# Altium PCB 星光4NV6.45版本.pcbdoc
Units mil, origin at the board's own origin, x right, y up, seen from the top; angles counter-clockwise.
Board outline 3937.01 x 2047.24 mil, 2 copper layers (Top Layer, Bottom Layer), stack 62.206 mil thick; 34 components, 26 nets, 163 pads, 100 vias.
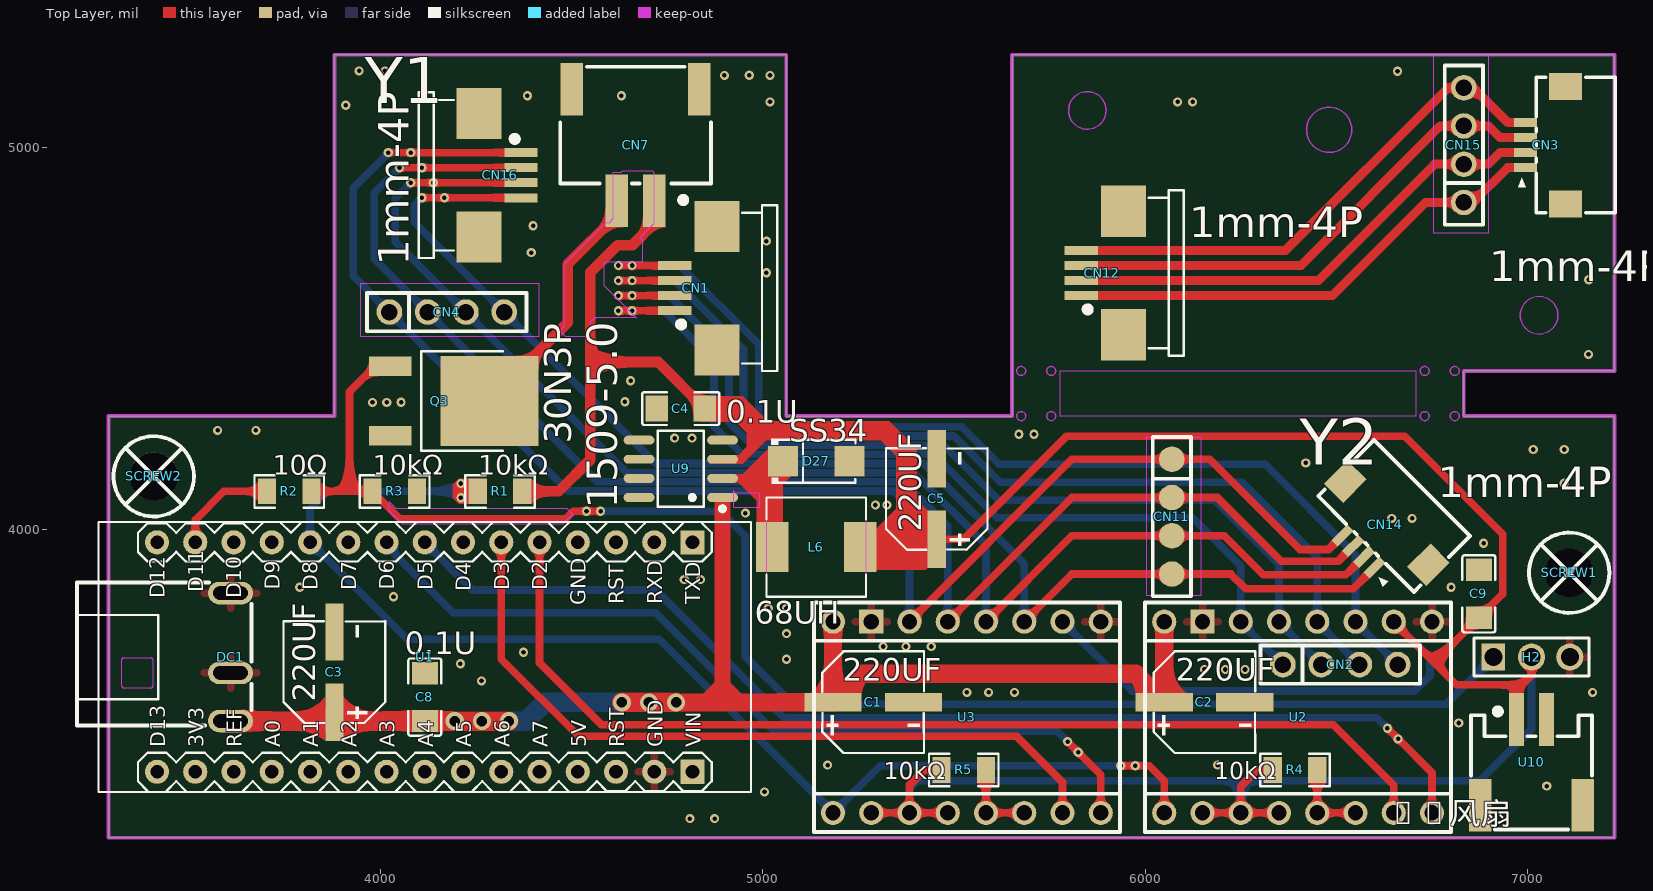
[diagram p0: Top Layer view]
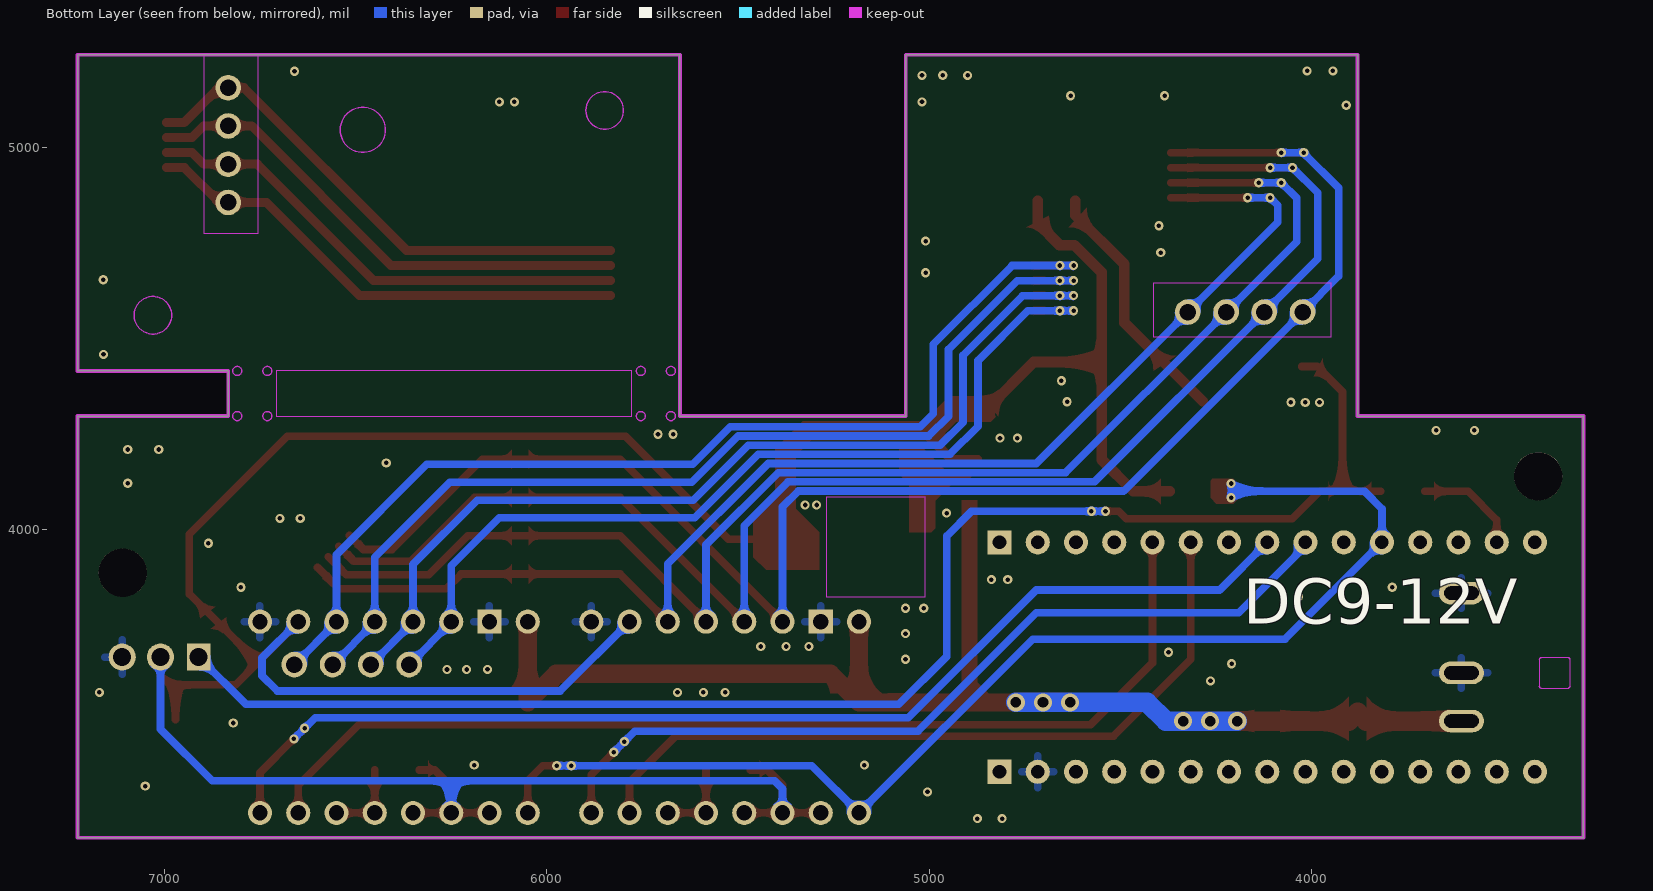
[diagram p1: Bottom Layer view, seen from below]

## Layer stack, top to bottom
Top Solder Mask Layer: solder mask 0.394, Dk 3.3
Top Layer: signal copper 1.379
Dielectric1: surface 59.449, FR4, Dk 4.5
Bottom Layer: signal copper 1.378
Bottom Solder Mask Layer: solder mask 0.394, Dk 3.3

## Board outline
3290,3195 3290,3293.43 3290,4297.36 3880.55,4297.36 3880.55,5242.24 5061.65,5242.24 5061.65,4297.36 5652.2,4297.36 5652.2,5242.24 7227.01,5242.24 7227.01,4415.47 6833.31,4415.47 6833.31,4297.36 7227.01,4297.36 7227.01,3293.43 7227.01,3195

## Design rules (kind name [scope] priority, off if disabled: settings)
BoardOutlineClearance copperThickness1oz [All] p0: genericclearance=10 ignorepadtopadclearanceinfootprint=FALSE except(0: Arc-SplitContinuation Track-SplitContinuation SMDPad-SplitContinuation THPad-SplitContinuation Via-SplitContinuation Fill-SplitContinuation Poly-SplitContinuation Region-SplitContinuation Text-SplitContinuation)
BoardOutlineClearance copperThickness2oz [All] p0: genericclearance=10 ignorepadtopadclearanceinfootprint=FALSE except(0: Arc-SplitContinuation Track-SplitContinuation SMDPad-SplitContinuation THPad-SplitContinuation Via-SplitContinuation Fill-SplitContinuation Poly-SplitContinuation Region-SplitContinuation Text-SplitContinuation)
BoardOutlineClearance Plane_innerPlane [All] p0: genericclearance=10 ignorepadtopadclearanceinfootprint=FALSE except(0: Arc-SplitContinuation Track-SplitContinuation SMDPad-SplitContinuation THPad-SplitContinuation Via-SplitContinuation Fill-SplitContinuation Poly-SplitContinuation Region-SplitContinuation Text-SplitContinuation)
BoardOutlineClearance Copper_copperRegion [All] p0: genericclearance=10 ignorepadtopadclearanceinfootprint=FALSE except(0: Arc-SplitContinuation Track-SplitContinuation SMDPad-SplitContinuation THPad-SplitContinuation Via-SplitContinuation Fill-SplitContinuation Poly-SplitContinuation Region-SplitContinuation Text-SplitContinuation)
BoardOutlineClearance Copper_copperRegion1 [All] p0: genericclearance=10 ignorepadtopadclearanceinfootprint=FALSE except(0: Arc-SplitContinuation Track-SplitContinuation SMDPad-SplitContinuation THPad-SplitContinuation Via-SplitContinuation Fill-SplitContinuation Poly-SplitContinuation Region-SplitContinuation Text-SplitContinuation)
BoardOutlineClearance otherClearance [All] p0: genericclearance=10 ignorepadtopadclearanceinfootprint=FALSE except(0: Arc-SplitContinuation Track-SplitContinuation SMDPad-SplitContinuation THPad-SplitContinuation Via-SplitContinuation Fill-SplitContinuation Poly-SplitContinuation Region-SplitContinuation Text-SplitContinuation)
Clearance copperThickness1oz [All] p1: gap=7 ignorepadtopadclearanceinfootprint=FALSE
Clearance copperThickness2oz [All] p1: gap=7 ignorepadtopadclearanceinfootprint=FALSE
Clearance Plane_innerPlane [All] p1: gap=7 ignorepadtopadclearanceinfootprint=FALSE
Clearance Copper_copperRegion [All] p1: gap=7 ignorepadtopadclearanceinfootprint=FALSE
Clearance Copper_copperRegion1 [All] p1: gap=7 ignorepadtopadclearanceinfootprint=FALSE
Clearance otherClearance [All] p1: gap=7 ignorepadtopadclearanceinfootprint=FALSE
DiffPairsRouting differentialPair [All] p1: maxuncoupledlength=10 minlimit=5.9843 maxlimit=Infinity mostfreqgap=5.9843 toplayer_minwidth=5 toplayer_prefwidth=10 toplayer_maxwidth=100 bottomlayer_minwidth=5 bottomlayer_prefwidth=10 bottomlayer_maxwidth=100
PasteMaskExpansion pasteMaskExpansion [All] p1: expansion=0
PlaneConnect innerPlane [All] p1: planeconnectstyle=Relief reliefexpansion=20 reliefentries=4 reliefconductorwidth=10 reliefairgap=10
PolygonConnect copperRegion [All] p1: connectstyle=Relief reliefentries=4 reliefconductorwidth=10 polygonreliefangle="90 Angle" airgapwidth=10
PolygonConnect copperRegion1 [All] p1: connectstyle=Relief reliefentries=4 reliefconductorwidth=19.685 polygonreliefangle="90 Angle" airgapwidth=10
RoutingVias viaSize [All] p1: viastyle="Through Hole" holewidth=12.0078 minholewidth=11.811 maxholewidth=248.0314 width=12.0078 minwidth=11.811 maxwidth=248.0314
SolderMaskExpansion solderMaskExpansion [All] p1: useseparateexpansions=TRUE expansion=2.0079 expansionbottom=2.0079
Width copperThickness1oz [All] p1: maxlimit=100 minlimit=5 preferedwidth=20
Width copperThickness2oz [All] p1: maxlimit=100 minlimit=5 preferedwidth=10

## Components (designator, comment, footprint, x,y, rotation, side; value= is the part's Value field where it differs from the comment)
C1 "" CAP-SMD_BD6.3-L6.6-W6.6-FD-1 5289.21,3549.33 r0 top
C2 "" CAP-SMD_BD6.3-L6.6-W6.6-FD-1 6155.36,3549.33 r0 top
C3 "220uF" CAP-SMD_BD6.3-L6.6-W6.6-FD-1 3880.55,3628.07 r90 top
C4 "100nF" C1206 4786.06,4317.05 r0 top
C5 "" CAP-SMD_BD6.3-L6.6-W6.6-FD-1 5455.35,4080.83 r90 top
C8 "" C1206 4116.77,3562.82 r270 top
C9 "" C1206 6872.68,3832.8 r270 top
CN1 "" FPC-SMD_4P-P1.00_AFA07-S04ECC-00 4825.43,4632.01 r90 top
CN2 "" HDR-TH_4P-P2.54-V-F#1 6510.47,3647.76 r0 top
CN3 "" FPC-SMD_4P-P1.00_10A20L04P 7049.84,5006.02 r90 top
CN4 "" HDR-TH_4P-P2.54-V-F#1 4174.37,4569.45 r0 top
CN7 "" CONN-SMD_2P-P2.54_MEGASTAR_ZX-XH2.54-2PWT 4667.95,5006.02 r180 top
CN11 "" HDR-TH_4P-P2.54-V-F#2 6070,4034.45 r270 top
CN12 "" FPC-SMD_4P-P1.00_AFA07-S04ECC-00 5888.43,4671.38 r90 top
CN14 "" FPC-SMD_4P-P1.00_10A20L04P 6597.09,3982.4 r135 top
CN15 "" HDR-TH_4P-P2.54-V-F#1 6833.31,5006.02 r90 top
CN16 "" FPC-SMD_4P-P1.00_AFA07-S04ECC-00 4313.62,4927.28 r270 top
D27 "" SMA_L4.3-W2.6-LS5.2-RD 5140.39,4179.25 r0 top
DC1 "" DC-IN-TH_DC044 3608.9,3667.44 r0 top
H2 "" HDR-TH_3P-P2.54-V-M-1 7010.47,3667.44 r0 top
L6 "" IND-SMD_L7.1-W6.6_H5.0 5140.39,3954.84 r180 top
Q3 "" TO-252-2_L6.6-W6.1-P4.60-LS10.0-BR-CW 4156.14,4336.73 r180 top
R1 "10kΩ" R1206 4313.62,4100.51 r0 top
R2 "10Ω" R1206 3762.44,4100.51 r180 top
R3 "10kΩ" R1206 4038.03,4100.51 r180 top
R4 "10kΩ" R1206 6392.02,3372.17 r180 top
R5 "10kΩ" R1206 5525.87,3372.17 r180 top
SCREW1 "" M3螺丝 7108.9,3887.91 r0 top
SCREW2 "" M3螺丝 3408.11,4139.88 r0 top
U1 "" COMM-TH_ARDUINO_NANO 4116.77,3667.44 r0 top
U2 "" DIP-16_L20.3-W15.2-P2.54_LS12.7_A4988 6400.24,3509.96 r90 top
U3 "" DIP-16_L20.3-W15.2-P2.54_LS12.7_A4988 5534.09,3509.96 r90 top
U9 "" SOIC-8_L4.9-W3.9-P1.27-LS6.0-BL 4786.06,4159.57 r90 top
U10 "" CONN-SMD_ZX-PH2.0-WT2P 7010.47,3391.85 r0 top

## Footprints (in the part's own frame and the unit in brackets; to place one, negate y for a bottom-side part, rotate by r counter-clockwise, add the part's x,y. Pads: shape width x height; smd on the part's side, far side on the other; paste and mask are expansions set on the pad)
C1206 [mm]
  rect 1.485x1.728 smd: 1(-1.593,0) 2(1.593,0)
  silkscreen extent -2.56,-1.09 2.56,1.09
CAP-SMD_BD6.3-L6.6-W6.6-FD-1 [mm]
  rect 3.8x1.2 smd: 1(-2.67,0) 2(2.67,0)
  silkscreen extent -3.38,-3.38 3.38,3.38
COMM-TH_ARDUINO_NANO [mm]
  rect 1.6x1.6 hole 0.9: 1(17.78,7.62) 30(17.78,-7.62)
  round 1.6 hole 0.9: 2(15.24,7.62) 4(10.16,7.62) 6(5.08,7.62) 8(0,7.62) 10(-5.08,7.62) 12(-10.16,7.62) 14(-15.24,7.62) 15(-17.78,7.62) 16(-17.78,-7.62) 18(-12.7,-7.62) 20(-7.62,-7.62) 22(-2.54,-7.62) 24(2.54,-7.62) 26(7.62,-7.62) 28(12.7,-7.62) 29(15.24,-7.62)
  round 1.6 hole 0.9 copper offset 0,0: 3(12.7,7.62)
  round 1.6 hole 0.9 copper offset -0.001,0: 5(7.621,7.62) 7(2.541,7.62) 9(-2.539,7.62) 11(-7.619,7.62) 13(-12.699,7.62)
  round 1.6 hole 0.9 copper offset 0.001,0: 17(-15.241,-7.62) 19(-10.161,-7.62) 21(-5.081,-7.62) 23(-0.001,-7.62) 25(5.079,-7.62) 27(10.159,-7.62)
  silkscreen extent -23.11,-8.97 21.67,8.97
CONN-SMD_2P-P2.54_MEGASTAR_ZX-XH2.54-2PWT [mm]
  rect 1.5x3.5 smd: 1(-1.25,3.7) 2(1.25,3.7) 3(-4.23,-3.7) 4(4.23,-3.7)
  silkscreen extent -5,-5.21 5,3.85
CONN-SMD_ZX-PH2.0-WT2P [mm]
  rect 1x3.5 smd: 1(-1,2.85) 2(1,2.85)
  rect 1.5x3.5 smd: 3(-3.4,-2.85) 4(3.4,-2.85)
  silkscreen extent -4.02,-4.44 4.02,3.59
DC-IN-TH_DC044 [mm]
  oval 3x1.5 hole 0.9 slot 2.3 at 0 deg: 2(0,4.25) 3(0,-1.05) 4(0,-4.25)
  Board Outline Layer lines w0.003: -7.209,-1.939 -7.209,-0.161 cw(c-7.082,-0.161) -7.082,-0.034 -5.304,-0.034 cw(c-5.304,-0.161) -5.177,-0.161 -5.177,-1.939 cw(c-5.304,-1.939) -5.304,-2.066 -7.082,-2.066 cw(c-7.082,-1.939) -7.209,-1.939
  Board Outline Layer region: -7.209,-1.939 -7.209,-0.161 -7.199,-0.112 -7.172,-0.071 -7.131,-0.044 -7.082,-0.034 -7.082,-0.034 -5.304,-0.034 -5.255,-0.044 -5.214,-0.071 -5.187,-0.112 -5.177,-0.161 -5.177,-0.161 -5.177,-1.939 -5.187,-1.988 -5.214,-2.029 -5.255,-2.056 -5.304,-2.066 -5.304,-2.066 -7.082,-2.066 -7.131,-2.056 -7.172,-2.029 -7.199,-1.988 -7.209,-1.939
  Board Outline Layer region: -7.209,-1.939 -7.209,-0.161 -7.199,-0.112 -7.172,-0.071 -7.131,-0.044 -7.082,-0.034 -7.082,-0.034 -5.304,-0.034 -5.255,-0.044 -5.214,-0.071 -5.187,-0.112 -5.177,-0.161 -5.177,-0.161 -5.177,-1.939 -5.187,-1.988 -5.214,-2.029 -5.255,-2.056 -5.304,-2.066 -5.304,-2.066 -7.082,-2.066 -7.131,-2.056 -7.172,-2.029 -7.199,-1.988 -7.209,-1.939
  silkscreen extent -10.2,-4.55 1.4,4.95
DIP-16_L20.3-W15.2-P2.54_LS12.7_A4988 [mm]
  round 1.6 hole 1.02: 1(-6.35,8.89) 2(-6.35,6.35) 3(-6.35,3.81) 4(-6.35,1.27) 5(-6.35,-1.27) 6(-6.35,-3.81) 7(-6.35,-6.35) 8(-6.35,-8.89) 9(6.35,-8.89) 10(6.35,-6.35) 11(6.35,-3.81) 12(6.35,-1.27) 13(6.35,1.27) 14(6.35,3.81) 16(6.35,8.89)
  rect 1.6x1.6 hole 1.02: 15(6.35,6.35)
  silkscreen extent -7.62,-10.16 7.62,10.16
FPC-SMD_4P-P1.00_10A20L04P [mm]
  rect 0.6x1.5 smd: 1(-1.5,1.4) 2(-0.5,1.4) 3(0.5,1.4) 4(1.5,1.4)
  rect 1.8x2.2 smd: 5(3.9,-1.263) 6(-3.9,-1.263)
  silkscreen extent -4.5,-4.56 4.5,1.9
FPC-SMD_4P-P1.00_AFA07-S04ECC-00 [mm]
  rect 0.6x2.2 smd: 1(-1.5,1.4) 2(-0.5,1.4) 3(0.5,1.4) 4(1.5,1.4)
  rect 3.4x3 smd: 5(4.1,-1.4) 6(-4.1,-1.4)
  silkscreen extent -5.5,-5.4 5.5,1.17
HDR-TH_3P-P2.54-V-M-1 [mm]
  rect 1.575x1.8 hole 1.2: 1(-2.54,0)
  round 1.8 hole 1.2: 2(0,0) 3(2.54,0)
  silkscreen extent -3.81,-1.27 3.81,1.27
HDR-TH_4P-P2.54-V-F#1 [mm]
  round 1.7 hole 1.1: 1(-3.81,0) 2(-1.27,0) 3(1.27,0) 4(3.81,0)
  silkscreen extent -5.29,-1.27 5.29,1.27
HDR-TH_4P-P2.54-V-F#2 [mm]
  round 1.7 smd: 1(-3.81,0) 2(-1.27,0) 3(1.27,0) 4(3.81,0)
  silkscreen extent -5.29,-1.27 5.29,1.27
IND-SMD_L7.1-W6.6_H5.0 [mm]
  rect 2.15x3.32 smd: 1(-2.913,0) 2(2.913,0)
  silkscreen extent -3.3,-3.3 3.3,3.3
M3螺丝 [mil]
  round 126 hole 126: 1(0,0)
  silkscreen extent -105,-105 105,105
R1206 [mil]
  rect 47.54x66.97 smd: 1(-58.22,0) 2(58.22,0)
  silkscreen extent -91,-42 91,42
SMA_L4.3-W2.6-LS5.2-RD [mm]
  rect 2x2 smd: 1(-2.2,0) 2(2.2,0)
  silkscreen extent -2.98,-1.5 2.6,1.5
SOIC-8_L4.9-W3.9-P1.27-LS6.0-BL [mm]
  oval 0.588x2.045 smd: 1(-1.905,-2.772) 2(-0.635,-2.772) 3(0.635,-2.772) 4(1.905,-2.772) 5(1.905,2.772) 6(0.635,2.772) 7(-0.635,2.772) 8(-1.905,2.772)
  silkscreen extent -2.8,-2.92 2.53,1.52
TO-252-2_L6.6-W6.1-P4.60-LS10.0-BR-CW [mm]
  rect 2.8x1.3 smd: 1(3.292,-2.3) 3(3.292,2.3)
  rect 6.5x6 smd: 2(-3.292,0)
  silkscreen extent -4.17,-3.3 1.23,3.3

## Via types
v1: diameter 24.02, hole 12.01, Top Layer to Bottom Layer, 94 vias
v2: diameter 47.24, hole 27.56, Top Layer to Bottom Layer, 6 vias

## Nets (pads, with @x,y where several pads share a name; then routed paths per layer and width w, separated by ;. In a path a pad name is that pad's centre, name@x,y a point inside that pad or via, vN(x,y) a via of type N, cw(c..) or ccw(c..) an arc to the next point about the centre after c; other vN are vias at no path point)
5V: C4.2 C5.1 C9.2 CN7.1 H2.2 L6.1 R1.2 R4.2 R5.2 U2.2 U2.3 U2.4 U2.10 U3.2 U3.3 U3.4 U3.10 U9.3 U10.1 | length 8164.9
  Top Layer w20: U3.2 U3.3 ; C5.1 5525.26,3975.71 5794.56,4245 6678.82,4245 6935,3988.82 6935,3832.42 C9.2 6768.05,3665.47 ; R5.2 5423.35,3372.17 5384.09,3332.91 U3.3 ; U3.4 U3.3 ; U2.2 U2.3 ; R4.2 6293.35,3372.17 6250.24,3329.06 U2.3 ; U2.4 U2.3 ; U2.10 6650.24,3758.58 6743.35,3665.47 ; U10.1 6971.1,3579.92 ; H2.2 7010.47,3619.29 6986.35,3595.17 ; 6743.35,3665.47 6768.05,3665.47 ; 6743.35,3665.47 6768.05,3640.77 ; 6768.05,3640.77 6768.05,3665.47 ; 6768.05,3640.77 6813.65,3595.17 6955.84,3595.17 ; 6955.84,3595.17 6971.1,3579.92 ; 6955.84,3595.17 6986.35,3595.17 ; 6971.1,3579.92 6986.35,3595.17
  Top Layer w27.56: R1.2 4466.69,4100.51 4550,4183.82 4550,4414.05 ; 4574.77,4438.82 4550,4414.05 ; CN7.1 4717.17,4802.01 4659.82,4744.66 4620.84,4744.66 4550,4673.82 4550,4463.82 ; C4.2 4726.99,4438.82 4575,4438.82 4550,4463.82 ; 4550,4414.05 4550,4463.82
  Bottom Layer w20: U3.3 5384.09,3322.91 5405,3343.82 6227.74,3343.82 ; U3.10 5965.24,3578.82 6705,3578.82 6745,3618.82 6745,3665.2 U2.10 ; U2.3 6250.24,3321.32 ; H2.2 7010.47,3479.29 6875,3343.82 6272.74,3343.82 ; 6227.74,3343.82 6250.24,3321.32 ; 6227.74,3343.82 6272.74,3343.82 ; 6250.24,3321.32 6272.74,3343.82
12V: C1.1 C2.1 C3.1 C8.2 DC1.4 U2.16 U3.16 U9.1 | length 3246.9
  Top Layer w47.24: v2(4773.79,3548.82) 5183.58,3548.82 C1.1 ; U3.16 C1.1 ; U2.16 C2.1 5975.75,3623.82 5258.58,3623.82 C1.1
  Top Layer w51.18: DC1.4 3857.72,3500.12 C3.1 3903.38,3500.12 C8.2 v2(4195.08,3500.12) v2(4265.9,3500.12) v2(4336.72,3500.12) ; v2(4632.15,3548.82) v2(4702.97,3548.82) v2(4773.79,3548.82)
  Bottom Layer w51.18: v2(4195.08,3500.12) v2(4265.9,3500.12) v2(4336.72,3500.12) 4381.82,3500.12 4430.51,3548.82 v2(4632.15,3548.82) v2(4702.97,3548.82) v2(4773.79,3548.82)
$1N38281: R5.1 U3.5 U3.6 | length 212.2
  Top Layer w20: R5.1 U3.5 U3.6
$1N38618: CN4.4 CN11.4 CN14.1 CN16.4 U3.11 | length 3512.4
  Top Layer w20: v1(4109.35,4868.23) v1(4168.06,4868.23) CN16.4 ; U3.11 5808.58,3884.45 CN11.4 6224.51,3884.45 6263.04,3845.91 6544.12,3845.91 CN14.1
  Bottom Layer w20: v1(4168.06,4868.23) v1(4109.35,4868.23) 4089.35,4848.23 4089.35,4804.46 CN4.4 4720.31,4173.5 5421.5,4173.5 5684.09,3910.91 U3.11
$1N38619: CN4.3 CN11.3 CN14.2 CN16.3 U3.12 | length 3734.1
  Top Layer w20: v1(4080,4907.6) v1(4138.71,4907.6) CN16.3 ; U3.12 5808.58,3984.45 CN11.3 6206.6,3984.45 6308.76,3882.28 6524.81,3882.28 CN14.2
  Bottom Layer w20: v1(4138.71,4907.6) v1(4080,4907.6) 4040,4867.6 4040,4753.82 CN4.3 4644.33,4149.49 5395.51,4149.49 5584.09,3960.91 U3.12
$1N38620: CN4.2 CN11.2 CN14.3 CN16.2 U3.13 | length 3961.3
  Top Layer w20: v1(4050.65,4946.97) v1(4109.35,4946.97) CN16.2 ; U3.13 5808.58,4084.45 CN11.2 6189.37,4084.45 6356.2,3917.62 6504.46,3917.62 CN14.3
  Bottom Layer w20: v1(4109.35,4946.97) v1(4050.65,4946.97) 3985,4881.32 3985,4708.82 CN4.2 4568.35,4125.47 5369.53,4125.47 5484.09,4010.91 U3.13
$1N38622: CN4.1 CN11.1 CN14.4 CN16.1 U3.14 | length 4190.7
  Top Layer w20: v1(4021.29,4986.33) v1(4080,4986.33) CN16.1 ; U3.14 5808.58,4184.45 CN11.1 6169.37,4184.45 6405,3948.82 6479.99,3948.82 CN14.4
  Bottom Layer w20: v1(4080,4986.33) 4022.51,4986.33 3930,4893.82 3930,4663.82 CN4.1 4492.36,4101.46 5342.6,4101.46 5384.09,4059.96 U3.14
$1N39292: R4.1 U2.5 U2.6 | length 212.2
  Top Layer w20: R4.1 U2.5 U2.6
$1N39467: CN1.4 CN2.4 U2.11 | length 2792.9
  Top Layer w20: v1(4623.04,4691.06) v1(4658.9,4691.06) CN1.4@4730.94,4691.06 ; CN2.4@6662.44,3647.76 CN2.4@6668.35,3647.76
  Bottom Layer w20: v1(4623.04,4691.06) v1(4658.9,4691.06) 4783.92,4691.06 4990.09,4484.89 4990.09,4303.72 5024.25,4269.57 5520.43,4269.57 5618.9,4171.1 6313.7,4171.1 6550.24,3934.56 U2.11 6550.24,3757.99 CN2.4
$1N39468: CN1.3 CN2.3 U2.12 | length 2664.2
  Top Layer w20: v1@4622.14,4651.69 v1(4658.9,4651.69) CN1.3@4730.94,4651.69
  Bottom Layer w20: v1(4623.04,4651.69) v1(4658.9,4651.69) 4770.19,4651.69 4950,4471.88 4950,4296.82 5001.27,4245.55 5499.45,4245.55 5620.92,4124.08 6254.15,4124.08 6450.24,3927.98 U2.12 6450.24,3757.99 CN2.3
$1N39469: CN1.1 CN2.1 U2.14 | length 2415.7
  Top Layer w20: v1(4623.04,4572.96) v1(4658.9,4572.96) CN1.1@4730.94,4572.96
  Bottom Layer w20: v1(4623.04,4572.96) v1(4658.9,4572.96) 4742.65,4572.96 4872.76,4442.86 4872.76,4271.06 4946.3,4197.52 5447.48,4197.52 5613.7,4031.3 6124.63,4031.3 6250.24,3905.69 U2.14 6250.24,3757.99 CN2.1
$1N39470: CN1.2 CN2.2 U2.13 | length 2535.3
  Top Layer w20: v1@4623.94,4612.32 v1(4658.9,4612.32) CN1.2@4730.94,4612.32
  Bottom Layer w20: v1(4623.04,4612.32) v1(4658.9,4612.32) 4756.5,4612.32 4912.05,4456.76 4912.05,4281.76 4972.28,4221.54 5473.46,4221.54 5617.49,4077.51 6182.29,4077.51 6350.24,3909.56 U2.13 6350.24,3757.99 CN2.2
$1N40367: CN7.2 Q3.2 | length 661.6
  Top Layer w27.56: Q3.2 4490,4540.98 4490,4694.31 4618.74,4823.05 CN7.2
$1N40669: H2.1 Q3.1 R2.1 R3.2 | length 4045.4
  Top Layer w20: R2.1 3897.44,4100.51 ; Q3.1 3985.99,4427.28 3920,4361.29 3920,4123.07 ; v1(4576.5,4048.82) v1(4539.71,4048.82) 4505,4048.82 4485,4028.82 4051.5,4028.82 R3.2 3942.56,4100.51 ; 3897.44,4100.51 3920,4123.07 ; 3897.44,4100.51 3942.56,4100.51 ; 3920,4123.07 3942.56,4100.51
  Bottom Layer w20: v1(4539.71,4048.82) v1(4576.5,4048.82) 4890,4048.82 4955,3983.82 4955,3668.82 5080,3543.82 6786.85,3543.82 H2.1
$1N43520: D27.1 L6.2 U9.2
$1N45498: CN3.4 CN12.4 CN15.4 | length 1375.4
  Top Layer w23.62: CN12.4 6366.61,4730.43 6792.2,5156.02 CN15.4 6857.8,5156.02 6948.74,5065.08 CN3.4
$1N45502: CN3.3 CN12.3 CN15.3 | length 1325.1
  Top Layer w23.62: CN12.3 6407.24,4691.06 6772.2,5056.02 CN15.3 6897.8,5056.02 6928.11,5025.71 CN3.3
$1N45507: CN3.2 CN12.2 CN15.2 | length 1300
  Top Layer w23.62: CN12.2 6452.87,4651.69 6757.2,4956.02 CN15.2 6897.2,4956.02 6927.52,4986.34 CN3.2
$1N45512: CN3.1 CN12.1 CN15.1 | length 1300
  Top Layer w23.62: CN12.1 6489.62,4612.33 6733.31,4856.02 CN15.1 6857.2,4856.02 6948.15,4946.97 CN3.1
D2/X-STEP: U1.5 U2.7 | length 2753.3
  Top Layer w20: U1.5 4416.77,3652.05 4578.82,3490 6492.02,3490 6650.24,3331.78 U2.7
D3/Y-STEP: U1.6 U3.7 | length 1986
  Top Layer w20: U1.6 4316.77,3662.05 4518.82,3460 5663.82,3460 5784.09,3339.72 U3.7
D5/X-DIR: U1.8 U2.8 | length 3027.5
  Top Layer w20: v1(6633.47,3481.49) v1(6661.51,3453.45) 6750.24,3364.73 U2.8
  Bottom Layer w20: U1.8 4241.4,3842.82 4721,3842.82 5055,3508.82 6606.14,3508.82 v1(6633.47,3481.49) v1(6661.51,3453.45)
D6/Y-DIR: U1.9 U3.8 | length 2259
  Top Layer w20: v1(5797.33,3446.49) v1(5825.37,3418.45) 5884.09,3359.72 U3.8
  Bottom Layer w20: U1.9@4013.69,3961.25 4191.63,3783.31 4720.51,3783.31 5030,3473.82 5770,3473.82 v1(5797.33,3446.49) v1(5825.37,3418.45)
D8/EN: R1.1 U1.11 U2.1 U3.1 | length 3289.8
  Top Layer w20: v1(5936.52,3383.15) v1(5974.33,3383.15) 6010.67,3383.15 6050.24,3343.58 U2.1
  Bottom Layer w20: v1(5974.33,3383.15) v1(5936.52,3383.15) 5307.28,3383.15 U3.1 4730.24,3713.82 4070.39,3713.82 U1.11 3816.77,4055.59 3862.5,4101.32 4191.14,4101.32 ; 4191.14,4101.32 v1(4211.14,4121.32) v1(4211.14,4083.82) 4193.64,4101.32 4191.14,4101.32
D11/PWM: R2.2 U1.14 | length 276.6
  Top Layer w20: U1.14 3516.77,4025.59 3591.69,4100.51 R2.2
GND: C1.2 C2.2 C3.2 C4.1 C5.2 C8.1 C9.1 CN1.5 CN1.6 CN3.5 CN3.6 CN7.3 CN7.4 CN12.5 CN12.6 CN14.5 CN14.6 CN16.5 CN16.6 D27.2 DC1.2 DC1.3 H2.3 Q3.3 R3.1 U1.29 U2.9 U2.15 U3.9 U3.15 U9.4 U9.5 U9.6 U9.7 U9.8 U10.2 U10.3 U10.4
  other v1: 4810,3245 4874.41,3245 5005,3315 7050,3330 5170,3385 6190,3385 6820,3495 5534.09,3574.9 5590.98,3574.9 5658.52,3574.9 7170,3575 4265,3605 6155.36,3635.18 6210,3635 6261.37,3635 4210,3650 5062.52,3661.7 4375,3680 5315,3695 5374.69,3695 5441.14,3695 5062.52,3728.69 5015,3795 5062.52,3795 4035,3825 3790,3850 6800,3850 4795,3870 4837.86,3870 6885,3965 6645,4030 6698.27,4030 4955.18,4043.76 5295,4065 5325,4065 7095.9,4121.88 6420,4175 7015,4210 7095.9,4210 4770,4240 4815.48,4240 5670,4250 5709.73,4250 3575,4260 3675.22,4260 3980,4333.19 4017.5,4333.19 4055,4333.82 4640,4335 4655,4390 7159.37,4458.82 7160,4653.82 5010,4672.38 4395,4725 5010,4755 4400,4795 3910,5110 5019.37,5118.82 6085,5118.82 6124.37,5118.82 4385,5135 4630.96,5135 4900,5188.19 5019.37,5188.19 4965,5188.82 6660,5198.82 3945,5200 4012.52,5200
pads on no net: SCREW1.1 SCREW2.1 U1.1 U1.2 U1.3 U1.4 U1.7 U1.10 U1.12 U1.13 U1.15 U1.16 U1.17 U1.18 U1.19 U1.20 U1.21 U1.22 U1.23 U1.24 U1.25 U1.26 U1.27 U1.28 U1.30

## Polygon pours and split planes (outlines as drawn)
GND on Top Layer (solid, remove dead copper, pour order 0): 3100,5350 7380,5350 7380,3100 3100,3100
GND on Bottom Layer (solid, remove dead copper, pour order 2): 3000,5450 7430,5450 7430,3000 3000,3000

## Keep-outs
Top Layer:
  region: 4634.12,4939.12 4710.88,4939.12 4715,4935 4715,4799.84 4679.14,4763.98 4685,4758.12 4685,4700 4590,4700 4585,4695 4585,4640 4670,4555 4562.62,4555 4550,4542.38 4550,4515 4540,4505 4485.92,4505 4469.97,4520.95 4481.35,4532.33 4481.35,4694.31 4589.79,4802.74 4598.44,4802.74 4610,4814.31 4610,4935 4630,4935
  region: 4923.09,4102.7 4923.09,4059.74 4992.1,4059.74 4992.1,4093.81 4989.56,4096.35 4929.44,4096.35
  region: 4023.8,4073.37 4040.88,4056.3 4488.36,4056.3 4503.89,4040.77 4477.22,4014.1 4058.7,4014.1 4023.8,4049
  region: 6004.75,4242.72 6145,4242.72 6145,3827.14 6004.75,3827.14
Board Outline Layer:
  region: 6540.51,5045.91 cw(c6481.46,5045.91) 6422.4,5045.91 cw(c6481.46,5045.91)
  circle w0.1: c6481.46,5045.91 r59.06
  region: 6540.51,5045.91 cw(c6481.46,5045.91) 6422.4,5045.91 cw(c6481.46,5045.91)
  region: 7079.37,4561.14 cw(c7030.16,4561.14) 6980.94,4561.14 cw(c7030.16,4561.14)
  circle w0.1: c7030.16,4561.14 r49.21
  region: 7079.37,4561.14 cw(c7030.16,4561.14) 6980.94,4561.14 cw(c7030.16,4561.14)
  region: 5898.27,5096.57 cw(c5849.06,5096.57) 5799.84,5096.57 cw(c5849.06,5096.57)
  circle w0.1: c5849.06,5096.57 r49.21
  region: 5898.27,5096.57 cw(c5849.06,5096.57) 5799.84,5096.57 cw(c5849.06,5096.57)
  region: 5766.38,4415.47 cw(c5754.57,4415.47) 5742.76,4415.47 cw(c5754.57,4415.47)
  circle w0.1: c5754.57,4415.47 r11.81
  region: 5766.38,4415.47 cw(c5754.57,4415.47) 5742.76,4415.47 cw(c5754.57,4415.47)
  region: 5687.64,4297.36 cw(c5675.83,4297.36) 5664.02,4297.36 cw(c5675.83,4297.36)
  circle w0.1: c5675.83,4297.36 r11.81
  region: 5687.64,4297.36 cw(c5675.83,4297.36) 5664.02,4297.36 cw(c5675.83,4297.36)
  region: 5766.38,4297.36 cw(c5754.57,4297.36) 5742.76,4297.36 cw(c5754.57,4297.36)
  circle w0.1: c5754.57,4297.36 r11.81
  region: 5766.38,4297.36 cw(c5754.57,4297.36) 5742.76,4297.36 cw(c5754.57,4297.36)
  region: 6742.76,4415.47 cw(c6730.94,4415.47) 6719.13,4415.47 cw(c6730.94,4415.47)
  circle w0.1: c6730.94,4415.47 r11.81
  region: 6742.76,4415.47 cw(c6730.94,4415.47) 6719.13,4415.47 cw(c6730.94,4415.47)
  region: 6821.5,4415.47 cw(c6809.69,4415.47) 6797.87,4415.47 cw(c6809.69,4415.47)
  circle w0.1: c6809.69,4415.47 r11.81
  region: 6821.5,4415.47 cw(c6809.69,4415.47) 6797.87,4415.47 cw(c6809.69,4415.47)
  region: 6742.76,4297.36 cw(c6730.94,4297.36) 6719.13,4297.36 cw(c6730.94,4297.36)
  circle w0.1: c6730.94,4297.36 r11.81
  region: 6742.76,4297.36 cw(c6730.94,4297.36) 6719.13,4297.36 cw(c6730.94,4297.36)
  region: 6821.5,4297.36 cw(c6809.69,4297.36) 6797.87,4297.36 cw(c6809.69,4297.36)
  circle w0.1: c6809.69,4297.36 r11.81
  region: 6821.5,4297.36 cw(c6809.69,4297.36) 6797.87,4297.36 cw(c6809.69,4297.36)
  region: 5778.19,4415.47 6707.32,4415.47 6707.32,4297.36 5778.19,4297.36
  region: 5778.19,4415.47 6707.32,4415.47 6707.32,4297.36 5778.19,4297.36
  region: 5687.64,4415.47 cw(c5675.83,4415.47) 5664.02,4415.47 cw(c5675.83,4415.47)
  circle w0.1: c5675.83,4415.47 r11.81
  region: 5687.64,4415.47 cw(c5675.83,4415.47) 5664.02,4415.47 cw(c5675.83,4415.47)
  region: 3949.37,4644.45 4414.37,4644.45 4414.37,4504.45 3949.37,4504.45
  region: 6754.84,5242.24 6897.2,5242.24 6897.2,4775.04 6754.84,4775.04
  region: 5010.47,4084.76 5270.31,4084.76 5270.31,3824.92 5010.47,3824.92
  lines w0.1: 5778.19,4297.36 6707.32,4297.36 6707.32,4415.47 5778.19,4415.47 5778.19,4297.36
  lines w10: 3290,3195 3290,3293.43 3290,4297.36 3880.55,4297.36 3880.55,5242.24 5061.65,5242.24 5061.65,4297.36 5652.2,4297.36 5652.2,5242.24 7227.01,5242.24 7227.01,4415.47 6833.31,4415.47 6833.31,4297.36 7227.01,4297.36 7227.01,3293.43 7227.01,3195 3290,3195

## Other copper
Top Layer:
  drawing of 138 lines, arcs and shapes, not listed
Bottom Layer:
  region net D8/EN: 3854.16,3944.19 3840.02,3930.05 3838.65,3931.31 3837.27,3932.37 3835.87,3933.25 3834.45,3933.96 3831.55,3934.96 3828.53,3935.52 3825.38,3935.76 3822.05,3935.83 3814.8,3936.01 3848.21,3969.41 3848.38,3962.16 3848.45,3958.84 3848.7,3955.68 3849.25,3952.66 3850.25,3949.76 3850.97,3948.34 3851.84,3946.94 3852.9,3945.56
  region net D8/EN: 3806.77,4010.32 3826.77,4010.32 3826.85,4008.46 3827.08,4006.73 3827.45,4005.12 3827.94,4003.62 3829.29,4000.86 3831.03,3998.33 3833.09,3995.93 3835.39,3993.53 3840.39,3988.27 3793.15,3988.27 3798.15,3993.53 3800.45,3995.93 3802.51,3998.33 3804.26,4000.86 3805.6,4003.62 3806.1,4005.12 3806.47,4006.73 3806.69,4008.46
  region net D6/Y-DIR: 4052.68,3936.4 4031.59,3929.21 4028.77,3931.68 4026.14,3933.33 4023.59,3934.37 4021.01,3934.98 4015.34,3935.72 4012.04,3936.23 4008.3,3937.11 4047.93,3962.83 4047.45,3959.26 4047.13,3955.66 4047.04,3952.1 4047.25,3948.6 4047.84,3945.24 4048.9,3942.05 4049.62,3940.54 4050.48,3939.09 4051.5,3937.71
  region net D5/X-DIR: 4154.16,3944.19 4140.02,3930.05 4138.65,3931.31 4137.27,3932.37 4135.87,3933.25 4134.45,3933.96 4131.55,3934.96 4128.53,3935.52 4125.38,3935.76 4122.05,3935.83 4114.8,3936.01 4148.21,3969.41 4148.38,3962.16 4148.45,3958.84 4148.7,3955.68 4149.25,3952.66 4150.25,3949.76 4150.97,3948.34 4151.84,3946.94 4152.9,3945.56
  region net 5V: 6240.24,3302.84 6260.24,3302.84 6260.31,3300.98 6260.54,3299.25 6260.91,3297.64 6261.41,3296.14 6262.75,3293.38 6264.49,3290.85 6266.56,3288.45 6268.86,3286.05 6273.86,3280.79 6226.61,3280.79 6231.62,3286.05 6233.92,3288.45 6235.98,3290.85 6237.72,3293.38 6239.07,3296.14 6239.56,3297.64 6239.93,3299.25 6240.16,3300.98
  region net 5V: 6687.63,3736.71 6673.49,3722.57 6672.12,3723.83 6670.73,3724.89 6669.34,3725.77 6667.92,3726.48 6665.02,3727.48 6662,3728.04 6658.84,3728.28 6655.52,3728.35 6648.26,3728.53 6681.67,3761.93 6681.85,3754.68 6681.92,3751.36 6682.16,3748.2 6682.71,3745.18 6683.72,3742.28 6684.43,3740.86 6685.31,3739.46 6686.37,3738.08
  region net $1N39467: 6540.24,3802.84 6560.24,3802.84 6560.31,3800.98 6560.54,3799.25 6560.91,3797.64 6561.41,3796.14 6562.75,3793.38 6564.49,3790.85 6566.56,3788.45 6568.86,3786.05 6573.86,3780.79 6526.61,3780.79 6531.62,3786.05 6533.92,3788.45 6535.98,3790.85 6537.72,3793.38 6539.07,3796.14 6539.56,3797.64 6539.93,3799.25 6540.16,3800.98
  region net $1N39467: 6587.37,3735 6571.75,3722.34 6570.37,3723.61 6568.98,3724.69 6567.6,3725.57 6566.21,3726.29 6563.37,3727.29 6560.44,3727.85 6557.37,3728.11 6554.11,3728.23 6550.63,3728.36 6546.88,3728.64 6581.73,3760.54 6581.68,3753.28 6581.7,3749.9 6581.93,3746.66 6582.48,3743.56 6583.49,3740.59 6584.2,3739.15 6585.07,3737.74 6586.12,3736.36
  region net $1N39468: 6440.24,3802.84 6460.24,3802.84 6460.31,3800.98 6460.54,3799.25 6460.91,3797.64 6461.41,3796.14 6462.75,3793.38 6464.49,3790.85 6466.56,3788.45 6468.86,3786.05 6473.86,3780.79 6426.61,3780.79 6431.62,3786.05 6433.92,3788.45 6435.98,3790.85 6437.72,3793.38 6439.07,3796.14 6439.56,3797.64 6439.93,3799.25 6440.16,3800.98
  region net $1N39468: 6487.37,3735 6471.75,3722.34 6470.37,3723.61 6468.98,3724.69 6467.6,3725.57 6466.21,3726.29 6463.37,3727.29 6460.44,3727.85 6457.37,3728.11 6454.11,3728.23 6450.63,3728.36 6446.88,3728.64 6481.73,3760.54 6481.68,3753.28 6481.7,3749.9 6481.93,3746.66 6482.48,3743.56 6483.49,3740.59 6484.2,3739.15 6485.07,3737.74 6486.12,3736.36
  region net $1N39470: 6340.24,3802.84 6360.24,3802.84 6360.31,3800.98 6360.54,3799.25 6360.91,3797.64 6361.41,3796.14 6362.75,3793.38 6364.49,3790.85 6366.56,3788.45 6368.86,3786.05 6373.86,3780.79 6326.61,3780.79 6331.62,3786.05 6333.92,3788.45 6335.98,3790.85 6337.72,3793.38 6339.07,3796.14 6339.56,3797.64 6339.93,3799.25 6340.16,3800.98
  region net $1N39470: 6387.37,3735 6371.75,3722.34 6370.37,3723.61 6368.98,3724.69 6367.6,3725.57 6366.21,3726.29 6363.37,3727.29 6360.44,3727.85 6357.37,3728.11 6354.11,3728.23 6350.63,3728.36 6346.88,3728.64 6381.73,3760.54 6381.68,3753.28 6381.7,3749.9 6381.93,3746.66 6382.48,3743.56 6383.49,3740.59 6384.2,3739.15 6385.07,3737.74 6386.12,3736.36
  region net $1N39469: 6240.24,3802.84 6260.24,3802.84 6260.31,3800.98 6260.54,3799.25 6260.91,3797.64 6261.41,3796.14 6262.75,3793.38 6264.49,3790.85 6266.56,3788.45 6268.86,3786.05 6273.86,3780.79 6226.61,3780.79 6231.62,3786.05 6233.92,3788.45 6235.98,3790.85 6237.72,3793.38 6239.07,3796.14 6239.56,3797.64 6239.93,3799.25 6240.16,3800.98
  region net $1N39469: 6287.37,3735 6271.75,3722.34 6270.37,3723.61 6268.98,3724.69 6267.6,3725.57 6266.21,3726.29 6263.37,3727.29 6260.44,3727.85 6257.37,3728.11 6254.11,3728.23 6250.63,3728.36 6246.88,3728.64 6281.73,3760.54 6281.68,3753.28 6281.7,3749.9 6281.93,3746.66 6282.48,3743.56 6283.49,3740.59 6284.2,3739.15 6285.07,3737.74 6286.12,3736.36
  region net 5V: 5374.09,3302.84 5394.09,3302.84 5394.17,3300.98 5394.4,3299.25 5394.77,3297.64 5395.27,3296.14 5396.61,3293.38 5398.35,3290.85 5400.41,3288.45 5402.71,3286.05 5407.72,3280.79 5360.47,3280.79 5365.47,3286.05 5367.78,3288.45 5369.84,3290.85 5371.58,3293.38 5372.92,3296.14 5373.42,3297.64 5373.79,3299.25 5374.02,3300.98
  region net D8/EN: 5207.34,3297.35 5221.49,3283.21 5220.23,3281.84 5219.17,3280.46 5218.29,3279.06 5217.57,3277.64 5216.57,3274.74 5216.02,3271.72 5215.78,3268.57 5215.71,3265.24 5215.53,3257.99 5182.12,3291.39 5189.37,3291.57 5192.7,3291.64 5195.86,3291.88 5198.87,3292.44 5201.78,3293.44 5203.19,3294.15 5204.59,3295.03 5205.97,3296.09
  region net D8/EN: 5146.7,3283.21 5160.84,3297.35 5162.22,3296.09 5163.6,3295.03 5165,3294.15 5166.41,3293.44 5169.32,3292.44 5172.33,3291.88 5175.49,3291.64 5178.81,3291.57 5186.07,3291.39 5152.66,3257.99 5152.48,3265.24 5152.41,3268.57 5152.17,3271.72 5151.62,3274.74 5150.61,3277.64 5149.9,3279.06 5149.02,3280.46 5147.96,3281.84
  region net 5V: 5821.49,3736.71 5807.34,3722.57 5805.97,3723.83 5804.59,3724.89 5803.19,3725.77 5801.78,3726.48 5798.87,3727.48 5795.86,3728.04 5792.7,3728.28 5789.37,3728.35 5782.12,3728.53 5815.53,3761.93 5815.71,3754.68 5815.78,3751.36 5816.02,3748.2 5816.57,3745.18 5817.57,3742.28 5818.29,3740.86 5819.17,3739.46 5820.23,3738.08
  region net $1N38618: 5674.09,3802.84 5694.09,3802.84 5694.17,3800.98 5694.4,3799.25 5694.77,3797.64 5695.27,3796.14 5696.61,3793.38 5698.35,3790.85 5700.41,3788.45 5702.71,3786.05 5707.72,3780.79 5660.47,3780.79 5665.47,3786.05 5667.78,3788.45 5669.84,3790.85 5671.58,3793.38 5672.92,3796.14 5673.42,3797.64 5673.79,3799.25 5674.02,3800.98
  region net $1N38619: 5574.09,3802.84 5594.09,3802.84 5594.17,3800.98 5594.4,3799.25 5594.77,3797.64 5595.27,3796.14 5596.61,3793.38 5598.35,3790.85 5600.41,3788.45 5602.71,3786.05 5607.72,3780.79 5560.47,3780.79 5565.47,3786.05 5567.78,3788.45 5569.84,3790.85 5571.58,3793.38 5572.92,3796.14 5573.42,3797.64 5573.79,3799.25 5574.02,3800.98
  region net $1N38620: 5474.09,3802.84 5494.09,3802.84 5494.17,3800.98 5494.4,3799.25 5494.77,3797.64 5495.27,3796.14 5496.61,3793.38 5498.35,3790.85 5500.41,3788.45 5502.71,3786.05 5507.72,3780.79 5460.47,3780.79 5465.47,3786.05 5467.78,3788.45 5469.84,3790.85 5471.58,3793.38 5472.92,3796.14 5473.42,3797.64 5473.79,3799.25 5474.02,3800.98
  region net $1N38622: 5374.09,3802.84 5394.09,3802.84 5394.17,3800.98 5394.4,3799.25 5394.77,3797.64 5395.27,3796.14 5396.61,3793.38 5398.35,3790.85 5400.41,3788.45 5402.71,3786.05 5407.72,3780.79 5360.47,3780.79 5365.47,3786.05 5367.78,3788.45 5369.84,3790.85 5371.58,3793.38 5372.92,3796.14 5373.42,3797.64 5373.79,3799.25 5374.02,3800.98
  region net $1N39469: 6321.19,3672.9 6335.33,3687.04 6336.84,3685.65 6338.35,3684.5 6339.86,3683.56 6341.39,3682.82 6342.93,3682.24 6344.49,3681.82 6347.7,3681.34 6351.07,3681.2 6354.64,3681.24 6358.46,3681.28 6362.57,3681.15 6327.07,3645.66 6326.95,3649.77 6326.99,3653.59 6327.02,3657.16 6326.89,3660.53 6326.41,3663.74 6325.98,3665.3 6325.41,3666.84 6324.66,3668.37 6323.73,3669.88 6322.57,3671.39
  region net $1N39470: 6421.19,3672.9 6435.33,3687.04 6436.84,3685.65 6438.35,3684.5 6439.86,3683.56 6441.39,3682.82 6442.93,3682.24 6444.49,3681.82 6447.7,3681.34 6451.07,3681.2 6454.64,3681.24 6458.46,3681.28 6462.57,3681.15 6427.07,3645.66 6426.95,3649.77 6426.99,3653.59 6427.02,3657.16 6426.89,3660.53 6426.41,3663.74 6425.98,3665.3 6425.41,3666.84 6424.66,3668.37 6423.73,3669.88 6422.57,3671.39
  region net $1N39468: 6521.19,3672.9 6535.33,3687.04 6536.84,3685.65 6538.35,3684.5 6539.86,3683.56 6541.39,3682.82 6542.93,3682.24 6544.49,3681.82 6547.7,3681.34 6551.07,3681.2 6554.64,3681.24 6558.46,3681.28 6562.57,3681.15 6527.07,3645.66 6526.95,3649.77 6526.99,3653.59 6527.02,3657.16 6526.89,3660.53 6526.41,3663.74 6525.98,3665.3 6525.41,3666.84 6524.66,3668.37 6523.73,3669.88 6522.57,3671.39
  region net $1N39467: 6621.19,3672.9 6635.33,3687.04 6636.84,3685.65 6638.35,3684.5 6639.86,3683.56 6641.39,3682.82 6642.93,3682.24 6644.49,3681.82 6647.7,3681.34 6651.07,3681.2 6654.64,3681.24 6658.46,3681.28 6662.57,3681.15 6627.07,3645.66 6626.95,3649.77 6626.99,3653.59 6627.02,3657.16 6626.89,3660.53 6626.41,3663.74 6625.98,3665.3 6625.41,3666.84 6624.66,3668.37 6623.73,3669.88 6622.57,3671.39
  region net $1N38622: 3985.08,4594.59 3999.23,4608.74 4000.74,4607.35 4002.25,4606.19 4003.76,4605.26 4005.28,4604.51 4006.83,4603.94 4008.39,4603.51 4011.6,4603.03 4014.97,4602.9 4018.54,4602.93 4022.36,4602.97 4026.47,4602.85 3990.97,4567.35 3990.84,4571.46 3990.88,4575.28 3990.92,4578.85 3990.79,4582.22 3990.3,4585.43 3989.88,4586.99 3989.31,4588.53 3988.56,4590.06 3987.62,4591.57 3986.47,4593.08
  region net $1N38622: 4063.66,4544.3 4049.51,4530.16 4048,4531.55 4046.49,4532.7 4044.98,4533.64 4043.46,4534.39 4041.91,4534.96 4040.35,4535.38 4037.14,4535.86 4033.77,4536 4030.2,4535.96 4026.38,4535.92 4022.27,4536.05 4057.77,4571.54 4057.9,4567.43 4057.86,4563.62 4057.82,4560.05 4057.95,4556.68 4058.44,4553.47 4058.86,4551.9 4059.43,4550.36 4060.18,4548.84 4061.12,4547.32 4062.27,4545.81
  region net $1N38620: 4085.08,4594.59 4099.23,4608.74 4100.74,4607.35 4102.25,4606.19 4103.76,4605.26 4105.28,4604.51 4106.83,4603.94 4108.39,4603.51 4111.6,4603.03 4114.97,4602.9 4118.54,4602.93 4122.36,4602.97 4126.47,4602.85 4090.97,4567.35 4090.84,4571.46 4090.88,4575.28 4090.92,4578.85 4090.79,4582.22 4090.3,4585.43 4089.88,4586.99 4089.31,4588.53 4088.56,4590.06 4087.62,4591.57 4086.47,4593.08
  region net $1N38620: 4163.66,4544.3 4149.51,4530.16 4148,4531.55 4146.49,4532.7 4144.98,4533.64 4143.46,4534.39 4141.91,4534.96 4140.35,4535.38 4137.14,4535.86 4133.77,4536 4130.2,4535.96 4126.38,4535.92 4122.27,4536.05 4157.77,4571.54 4157.9,4567.43 4157.86,4563.62 4157.82,4560.05 4157.95,4556.68 4158.44,4553.47 4158.86,4551.9 4159.43,4550.36 4160.18,4548.84 4161.12,4547.32 4162.27,4545.81
  region net $1N38619: 4185.08,4594.59 4199.23,4608.74 4200.74,4607.35 4202.25,4606.19 4203.76,4605.26 4205.28,4604.51 4206.83,4603.94 4208.39,4603.51 4211.6,4603.03 4214.97,4602.9 4218.54,4602.93 4222.36,4602.97 4226.47,4602.85 4190.97,4567.35 4190.84,4571.46 4190.88,4575.28 4190.92,4578.85 4190.79,4582.22 4190.3,4585.43 4189.88,4586.99 4189.31,4588.53 4188.56,4590.06 4187.62,4591.57 4186.47,4593.08
  region net $1N38619: 4263.66,4544.3 4249.51,4530.16 4248,4531.55 4246.49,4532.7 4244.98,4533.64 4243.46,4534.39 4241.91,4534.96 4240.35,4535.38 4237.14,4535.86 4233.77,4536 4230.2,4535.96 4226.38,4535.92 4222.27,4536.05 4257.77,4571.54 4257.9,4567.43 4257.86,4563.62 4257.82,4560.05 4257.95,4556.68 4258.44,4553.47 4258.86,4551.9 4259.43,4550.36 4260.18,4548.84 4261.12,4547.32 4262.27,4545.81
  region net $1N38618: 4285.08,4594.59 4299.23,4608.74 4300.74,4607.35 4302.25,4606.19 4303.76,4605.26 4305.28,4604.51 4306.83,4603.94 4308.39,4603.51 4311.6,4603.03 4314.97,4602.9 4318.54,4602.93 4322.36,4602.97 4326.47,4602.85 4290.97,4567.35 4290.84,4571.46 4290.88,4575.28 4290.92,4578.85 4290.79,4582.22 4290.3,4585.43 4289.88,4586.99 4289.31,4588.53 4288.56,4590.06 4287.62,4591.57 4286.47,4593.08
  region net $1N38618: 4363.66,4544.3 4349.51,4530.16 4348,4531.55 4346.49,4532.7 4344.98,4533.64 4343.46,4534.39 4341.91,4534.96 4340.35,4535.38 4337.14,4535.86 4333.77,4536 4330.2,4535.96 4326.38,4535.92 4322.27,4536.05 4357.77,4571.54 4357.9,4567.43 4357.86,4563.62 4357.82,4560.05 4357.95,4556.68 4358.44,4553.47 4358.86,4551.9 4359.43,4550.36 4360.18,4548.84 4361.12,4547.32 4362.27,4545.81
  region net 5V: 7020.47,3619.2 7000.47,3619.2 7000.38,3621.44 7000.1,3623.48 6999.65,3625.34 6999.05,3627.04 6998.3,3628.61 6997.41,3630.08 6995.29,3632.78 6992.78,3635.33 6989.98,3637.93 6986.99,3640.75 6983.9,3644 7037.05,3644 7033.96,3640.75 7030.96,3637.93 7028.16,3635.33 7025.65,3632.78 7023.53,3630.08 7022.65,3628.61 7021.9,3627.04 7021.29,3625.34 7020.84,3623.48 7020.57,3621.44
  region net $1N40669: 6878.57,3621.4 6868.87,3639.98 ccw(c6826.44,3671.8) 6879.47,3671.8 6910.39,3632.01 ccw(c6910.39,3578.97)
  region net $1N39467: 4673.31,4701.06 4673.31,4681.06 4670.66,4680.98 4668.16,4680.75 4663.78,4680.06 4660.56,4679.37 4658.9,4679.06 4658.9,4703.07 4660.56,4702.76 4663.78,4702.07 4668.16,4701.38 4670.66,4701.15
  region net $1N39467: 4644.49,4681.06 4644.49,4701.06 4647.14,4701.15 4649.64,4701.38 4654.02,4702.07 4657.24,4702.76 4658.9,4703.07 4658.9,4679.06 4657.24,4679.37 4654.02,4680.06 4649.64,4680.75 4647.14,4680.98
  region net $1N39468: 4644.49,4641.69 4644.49,4661.69 4647.14,4661.78 4649.64,4662.01 4654.02,4662.7 4657.24,4663.39 4658.9,4663.7 4658.9,4639.69 4657.24,4640 4654.02,4640.69 4649.64,4641.38 4647.14,4641.61
  region net $1N39468: 4673.31,4661.69 4673.31,4641.69 4670.66,4641.61 4668.16,4641.38 4663.78,4640.69 4660.56,4640 4658.9,4639.69 4658.9,4663.7 4660.56,4663.39 4663.78,4662.7 4668.16,4662.01 4670.66,4661.78
  region net $1N39470: 4644.49,4602.32 4644.49,4622.32 4647.14,4622.41 4649.64,4622.64 4654.02,4623.33 4657.24,4624.02 4658.9,4624.33 4658.9,4600.31 4657.24,4600.63 4654.02,4601.32 4649.64,4602.01 4647.14,4602.24
  region net $1N39470: 4673.31,4622.32 4673.31,4602.32 4670.66,4602.24 4668.16,4602.01 4663.78,4601.32 4660.56,4600.63 4658.9,4600.31 4658.9,4624.33 4660.56,4624.02 4663.78,4623.33 4668.16,4622.64 4670.66,4622.41
  region net $1N39469: 4644.49,4562.96 4644.49,4582.96 4647.14,4583.05 4649.64,4583.28 4654.02,4583.97 4657.24,4584.66 4658.9,4584.97 4658.9,4560.95 4657.24,4561.27 4654.02,4561.96 4649.64,4562.65 4647.14,4562.88
  region net $1N39469: 4673.31,4582.96 4673.31,4562.96 4670.66,4562.88 4668.16,4562.65 4663.78,4561.96 4660.56,4561.27 4658.9,4560.95 4658.9,4584.97 4660.56,4584.66 4663.78,4583.97 4668.16,4583.28 4670.66,4583.05
  region net $1N39467: 4637.45,4701.06 4637.45,4681.06 4634.8,4680.98 4632.3,4680.75 4627.92,4680.06 4624.7,4679.37 4623.04,4679.06 4623.04,4703.07 4624.7,4702.76 4627.92,4702.07 4632.3,4701.38 4634.8,4701.15
  region net $1N39468: 4637.45,4661.69 4637.45,4641.69 4634.8,4641.61 4632.3,4641.38 4627.92,4640.69 4624.7,4640 4623.04,4639.69 4623.04,4663.7 4624.7,4663.39 4627.92,4662.7 4632.3,4662.01 4634.8,4661.78
  region net $1N39470: 4637.45,4622.32 4637.45,4602.32 4634.8,4602.24 4632.3,4602.01 4627.92,4601.32 4624.7,4600.63 4623.04,4600.31 4623.04,4624.33 4624.7,4624.02 4627.92,4623.33 4632.3,4622.64 4634.8,4622.41
  region net $1N39469: 4637.45,4582.96 4637.45,4562.96 4634.8,4562.88 4632.3,4562.65 4627.92,4561.96 4624.7,4561.27 4623.04,4560.95 4623.04,4584.97 4624.7,4584.66 4627.92,4583.97 4632.3,4583.28 4634.8,4583.05
  region net D8/EN: 4221.14,4106.91 4201.14,4106.91 4201.05,4109.56 4200.83,4112.06 4200.13,4116.44 4199.44,4119.66 4199.13,4121.32 4223.15,4121.32 4222.83,4119.66 4222.14,4116.44 4221.45,4112.06 4221.23,4109.56
  region net D8/EN: 4208.02,4104.06 4193.88,4118.2 4195.69,4120.13 4197.3,4122.06 4199.91,4125.65 4201.7,4128.41 4202.65,4129.81 4219.63,4112.83 4218.23,4111.88 4215.47,4110.09 4211.88,4107.48 4209.95,4105.87
  region net D8/EN: 4193.88,4086.94 4208.02,4101.08 4209.95,4099.27 4211.88,4097.66 4215.47,4095.05 4218.23,4093.26 4219.63,4092.31 4202.65,4075.33 4201.7,4076.72 4199.91,4079.49 4197.3,4083.07 4195.69,4085
  region net D8/EN: 4201.14,4098.23 4221.14,4098.23 4221.23,4095.58 4221.45,4093.08 4222.14,4088.7 4222.83,4085.48 4223.15,4083.82 4199.13,4083.82 4199.44,4085.48 4200.13,4088.7 4200.83,4093.08 4201.05,4095.58
  region net $1N38622: 4065.59,4976.33 4065.59,4996.33 4068.24,4996.41 4070.74,4996.64 4075.12,4997.33 4078.34,4998.02 4080,4998.34 4080,4974.32 4078.34,4974.63 4075.12,4975.32 4070.74,4976.01 4068.24,4976.24
  region net $1N38620: 4094.95,4936.97 4094.95,4956.97 4097.59,4957.05 4100.1,4957.28 4104.48,4957.97 4107.69,4958.66 4109.35,4958.98 4109.35,4934.96 4107.69,4935.27 4104.48,4935.96 4100.1,4936.65 4097.59,4936.88
  region net $1N38619: 4076.88,4890.34 4062.74,4904.48 4064.55,4906.41 4066.16,4908.34 4068.77,4911.93 4070.56,4914.69 4071.51,4916.09 4088.49,4899.11 4087.1,4898.16 4084.33,4896.37 4080.75,4893.76 4078.81,4892.15
  region net $1N38619: 4094.41,4917.6 4094.41,4897.6 4091.76,4897.51 4089.26,4897.28 4084.88,4896.59 4081.66,4895.9 4080,4895.59 4080,4919.61 4081.66,4919.29 4084.88,4918.6 4089.26,4917.91 4091.76,4917.68
  region net $1N38619: 4124.3,4897.6 4124.3,4917.6 4126.95,4917.68 4129.45,4917.91 4133.83,4918.6 4137.05,4919.29 4138.71,4919.61 4138.71,4895.59 4137.05,4895.9 4133.83,4896.59 4129.45,4897.28 4126.95,4897.51
  region net $1N38618: 4153.65,4858.23 4153.65,4878.23 4156.3,4878.31 4158.8,4878.54 4163.19,4879.23 4166.4,4879.92 4168.06,4880.24 4168.06,4856.22 4166.4,4856.53 4163.19,4857.22 4158.8,4857.91 4156.3,4858.14
  region net $1N38618: 4106.24,4850.97 4092.09,4865.11 4093.91,4867.04 4095.51,4868.97 4098.12,4872.56 4099.91,4875.32 4100.86,4876.72 4117.85,4859.74 4116.45,4858.79 4113.69,4857 4110.1,4854.39 4108.17,4852.78
  region net $1N38618: 4123.76,4878.23 4123.76,4858.23 4121.12,4858.14 4118.61,4857.91 4114.23,4857.22 4111.01,4856.53 4109.35,4856.22 4109.35,4880.24 4111.01,4879.92 4114.23,4879.23 4118.61,4878.54 4121.12,4878.31
  region net $1N38620: 4047.53,4929.71 4033.39,4943.85 4035.2,4945.78 4036.81,4947.71 4039.42,4951.3 4041.2,4954.06 4042.15,4955.46 4059.14,4938.48 4057.74,4937.53 4054.98,4935.74 4051.39,4933.13 4049.46,4931.52
  region net $1N38620: 4065.05,4956.97 4065.05,4936.97 4062.41,4936.88 4059.9,4936.65 4055.52,4935.96 4052.31,4935.27 4050.65,4934.96 4050.65,4958.98 4052.31,4958.66 4055.52,4957.97 4059.9,4957.28 4062.41,4957.05
  region net $1N38622: 4019.39,4969.07 4004.03,4981.99 4005.68,4983.78 4006.82,4985.31 4007.63,4986.67 4008.27,4987.96 4009.64,4990.67 4010.69,4992.28 4012.21,4994.19 4030.37,4978.47 4028.75,4976.71 4027.38,4975.41 4025.02,4973.64 4022.6,4971.92 4021.14,4970.72
  region net $1N38622: 4035.7,4996.33 4035.7,4976.33 4033.05,4976.24 4030.55,4976.01 4026.17,4975.32 4022.95,4974.63 4021.29,4974.32 4021.29,4998.34 4022.95,4998.02 4026.17,4997.33 4030.55,4996.64 4033.05,4996.41
  region net $1N40669: 4562.09,4038.82 4562.09,4058.82 4564.74,4058.91 4567.24,4059.13 4571.62,4059.82 4574.84,4060.51 4576.5,4060.83 4576.5,4036.81 4574.84,4037.12 4571.62,4037.82 4567.24,4038.51 4564.74,4038.73
  region net $1N40669: 4590.91,4058.82 4590.91,4038.82 4588.26,4038.73 4585.76,4038.51 4581.38,4037.82 4578.16,4037.12 4576.5,4036.81 4576.5,4060.83 4578.16,4060.51 4581.38,4059.82 4585.76,4059.13 4588.26,4058.91
  region net $1N40669: 4554.12,4058.82 4554.12,4038.82 4551.47,4038.73 4548.97,4038.51 4544.59,4037.82 4541.37,4037.12 4539.71,4036.81 4539.71,4060.83 4541.37,4060.51 4544.59,4059.82 4548.97,4059.13 4551.47,4058.91
  region net D6/Y-DIR: 5780.07,3449.61 5794.21,3463.75 5796.14,3461.94 5798.07,3460.33 5801.66,3457.72 5804.42,3455.93 5805.82,3454.98 5788.84,3438 5787.89,3439.39 5786.1,3442.16 5783.49,3445.74 5781.88,3447.68
  region net D6/Y-DIR: 5814.59,3443.37 5800.45,3429.23 5798.51,3431.04 5796.58,3432.65 5793,3435.26 5790.23,3437.05 5788.84,3438 5805.82,3454.98 5806.77,3453.59 5808.56,3450.82 5811.17,3447.24 5812.78,3445.3
  region net D6/Y-DIR: 5808.11,3421.57 5822.25,3435.71 5824.19,3433.9 5826.12,3432.29 5829.7,3429.68 5832.47,3427.89 5833.86,3426.94 5816.88,3409.96 5815.93,3411.35 5814.14,3414.12 5811.53,3417.7 5809.92,3419.63
  region net D5/X-DIR: 6644.25,3456.57 6658.4,3470.71 6660.33,3468.9 6662.26,3467.29 6665.85,3464.68 6668.61,3462.89 6670,3461.94 6653.02,3444.96 6652.07,3446.35 6650.28,3449.12 6647.67,3452.7 6646.06,3454.63
  region net D5/X-DIR: 6616.21,3484.61 6630.35,3498.75 6632.29,3496.94 6634.22,3495.33 6637.8,3492.72 6640.57,3490.93 6641.96,3489.98 6624.98,3473 6624.03,3474.39 6622.24,3477.16 6619.63,3480.74 6618.02,3482.68
  region net D5/X-DIR: 6650.73,3478.37 6636.59,3464.23 6634.66,3466.04 6632.73,3467.65 6629.14,3470.26 6626.38,3472.05 6624.98,3473 6641.96,3489.98 6642.91,3488.59 6644.7,3485.82 6647.31,3482.24 6648.92,3480.3
  region net D8/EN: 5922.11,3373.15 5922.11,3393.15 5924.75,3393.23 5927.26,3393.46 5931.64,3394.15 5934.86,3394.84 5936.52,3395.15 5936.52,3371.14 5934.86,3371.45 5931.64,3372.14 5927.26,3372.83 5924.75,3373.06
  region net D8/EN: 5950.92,3393.15 5950.92,3373.15 5948.28,3373.06 5945.77,3372.83 5941.39,3372.14 5938.18,3371.45 5936.52,3371.14 5936.52,3395.15 5938.18,3394.84 5941.39,3394.15 5945.77,3393.46 5948.28,3393.23
  region net D8/EN: 5959.92,3373.15 5959.92,3393.15 5962.56,3393.23 5965.07,3393.46 5969.45,3394.15 5972.67,3394.84 5974.33,3395.15 5974.33,3371.14 5972.67,3371.45 5969.45,3372.14 5965.07,3372.83 5962.56,3373.06
  region net D8/EN: 4204.07,4128.39 cw(c4127,4293.83) 4127,4111.32 4129.5,4091.32 cw(c4129.5,3893.22) 4204.07,4076.75 4218.21,4090.89 cw(c4229.89,4102.57) 4218.21,4114.25
  region net 5V: 6260.24,3259.96 cw(c6420.66,3259.96) 6279.81,3336.75 6265.66,3350.89 cw(c6250.24,3366.32) 6234.81,3350.89 6220.67,3336.75 cw(c6079.81,3259.96) 6240.24,3259.96
  region net 5V: 6243.17,3314.25 ccw(c6194.44,3265.53) 6203.59,3333.82 6227.74,3343.82 6271.88,3333.82 ccw(c6271.88,3311.55) 6257.31,3328.39
  region net 5V: 6243.17,3328.39 ccw(c6228.59,3311.55) 6228.59,3333.82 6272.74,3343.82 6296.88,3333.82 ccw(c6306.03,3265.53) 6257.31,3314.25

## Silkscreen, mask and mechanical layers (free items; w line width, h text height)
Top Silkscreen Layer:
  text "Y1" at 3960,5115 h120
  text "1mm-4P" at 6115,4765 h78.74
  text "1mm-4P" at 4075,4690 h78.74 r90
  text "1mm-4P" at 6900,4650 h78.74
  text "0.1U" at 4905,4280 h59.06
  text "SS34" at 5070,4230 h59.06
  text "30N3P" at 4500,4225 h70.87 r90
  text "Y2" at 6405,4170 h120
  text "1mm-4P" at 6765,4085 h78.74
  text "1509-5.0" at 4620,4055 h78.74 r90
  text "220UF" at 5415,3995 h59.06 r90
  text "68UH" at 4980,3755 h59.06
  text "0.1U" at 4065,3675 h59.06
  text "220UF" at 5210,3605 h59.06
  text "220UF" at 6080,3605 h59.06
  text "220UF" at 3830,3550 h59.06 r90
  text "5V风扇" at 6635,3230 h59.06
Bottom Silkscreen Layer:
  text "DC9-12V" at 4180,3755 h118.11
Top Solder Mask Layer:
  text "星光4N V6.45版本   流浪的星星" at 3345,3220 h78.74
Mechanical Layer:
  circle w0.1: c6481.46,5045.91 r59.06
  circle w0.1: c7030.16,4561.14 r49.21
  circle w0.1: c5849.06,5096.57 r49.21
  circle w0.1: c5754.57,4415.47 r11.81
  circle w0.1: c5675.83,4297.36 r11.81
  circle w0.1: c5754.57,4297.36 r11.81
  circle w0.1: c6730.94,4415.47 r11.81
  circle w0.1: c6809.69,4415.47 r11.81
  circle w0.1: c6730.94,4297.36 r11.81
  circle w0.1: c6809.69,4297.36 r11.81
  circle w0.1: c5675.83,4415.47 r11.81
  lines w0.1: 5778.19,4297.36 6707.32,4297.36 6707.32,4415.47 5778.19,4415.47 5778.19,4297.36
